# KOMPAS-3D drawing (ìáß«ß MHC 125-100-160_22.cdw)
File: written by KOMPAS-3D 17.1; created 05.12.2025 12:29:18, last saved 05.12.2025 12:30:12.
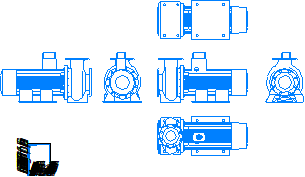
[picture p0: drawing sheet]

Sheet 1: A4, portrait

Title block, sheet 1: name: Насос MHC 125-100-160_22 / 22 кВт 3х380В; material: Сталь 10  ГОСТ 1050-88; mass: 326,95; sheets: 1; sheet format: A4

Views: Проекционный вид 2, Проекционный вид 3, Проекционный вид 4, Проекционный вид 5, Проекционный вид 6
Referenced files in \\adlc.lan\data\АДЛ_ПКД\3D-модели\ADL production\Насосы ГРАНПАМП\Насосы ГРАНПАМП серии МНС\KOMPAS 3D\: Насос MHC 125-100-160_22.m3d
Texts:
  Andrey
  АДЛ
Dimensions and other numbers on the sheet: 1:1; 1; 22 кВт 3х380В; 326,95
